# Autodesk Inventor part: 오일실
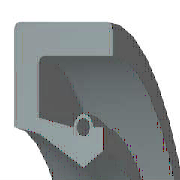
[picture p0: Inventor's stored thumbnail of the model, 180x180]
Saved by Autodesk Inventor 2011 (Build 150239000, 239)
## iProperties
IsCustomPart: 1
Created: 2009-02
Part Number: 오일실
Material: 고무
Description: 오일-실
Document SubType Name: Modeling
Standard: KS B 2804
Designer: SeoGD™[esajin.kr]
Standards Organization: KS
Language: ko-KR
Size Designation: S - 25 38 8
Categories: <MemberInstance><Categories><Category DisplayName="샤프트 부품" InternalName="7f7aeb1f-a693-4053-b835-cee3144e0d98" Mnemonic="SHFT"><Category DisplayName="실링" Intern
Density: 0.93 g/cm^3
Mass: 2.23721 g
Surface Area: 37.0166 cm^2
Volume: 2.4056 cm^3
Author: SeoGD™[esajin.kr]
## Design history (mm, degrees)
revolve "본체" stored, may be unused: angle "d17" = 90 deg
revolve "스프링1" stored, may be unused: angle "d18" = 90 deg
body "Solid1"
sketch "스케치1"
  geometry: L1 (0, 19)-(8, 19); L2 (8, 19)-(8, 17.75); L3 (8, 17.75)-(1.75, 17.75); L4 (0, 19)-(0, 14.6); L5 (0, 14.6)-(1.75, 14.25); L6 (1.75, 14.25)-(4.9, 12.5); L7 (4.9, 12.5)-(0, 12.5); L8 (6.3, 13.375)-(6.3, 14.6); L9 (0, 0)-(9.586, 0) reference; L10 (4.9, 12.5)-(6.3, 13.375); L11 (0, 18)-(0, -3) reference; L12 (-1.917, 0)-(11.503, 0) reference; L13 (4.2, 14.6)-(1.75, 15.09); L14 (1.75, 15.09)-(1.75, 17.75); L15 (6.3, 14.6)-(5.6, 14.6); C1 r 0.455 at (4.9, 14.6); A1 r 0.7 centre (4.9, 14.6) between (5.6, 14.6) and (4.2, 14.6)
  constraints: 26 end point, 5 horizontal alignment, 4 perpendicular, 2 centre point, 2 collinear, 2 horizontal, 2 parallel, 2 point on circle, 2 point on line, 2 vertical alignment, 1 coincident
  dimensions: "d0" = 38 diameter of L1 L9 (= SD2); "d1" = 26.75 diameter of L8.start L9 (= ABDM); "d2" = 1.25 distance of L1.end L2.end (computed from SD); "d3" = 0.91 diameter of C1 (= SPDI); "d4" = 1.4 diameter of A1 (= SPDA); "d5" = 25 diameter of L6.end L9 (= NND); "d6" = 28.5 diameter of L5.end L9 (= TKDM); "d7" = 29.2 diameter of L4.end L9 (= HLDM); "d8" = 4.9 distance from line of C1.centre L4 (= SPDST); "d9" = 6.3 distance between parallel lines of L8 L4 (= SDI); "d10" = 8 distance between parallel lines of L2 L4 (= SWDT); "d12" = 1.75 distance between parallel lines of L14 L4 (= SD)
fillet "모깎기1" dims "d11" = 0.3 (= RR)
other parameters: "SD2" = 38 [user parameter; used in 1 equation term], "SWDT" = 8 [user parameter; used in 1 equation term], "RR" = 0.3 [user parameter; used in 1 equation term], "SD" = 1.75 [user parameter; used in 2 equation terms], "NND" = 25 [user parameter; used in 1 equation term], "SPDA" = 1.4 [user parameter; used in 1 equation term], "SPDI" = 0.91 [user parameter; used in 1 equation term], "TKDM" = 28.5 [user parameter; used in 1 equation term], "HLDM" = 29.2 [user parameter; used in 1 equation term], "ABDM" = 26.75 [user parameter; used in 1 equation term], "SDI" = 6.3 [user parameter; used in 1 equation term], "SPDST" = 4.9 [user parameter; used in 1 equation term], "d13" = 0, "d14" = 0, "d15" = 0, "LAB" = 0.35 [user parameter]
